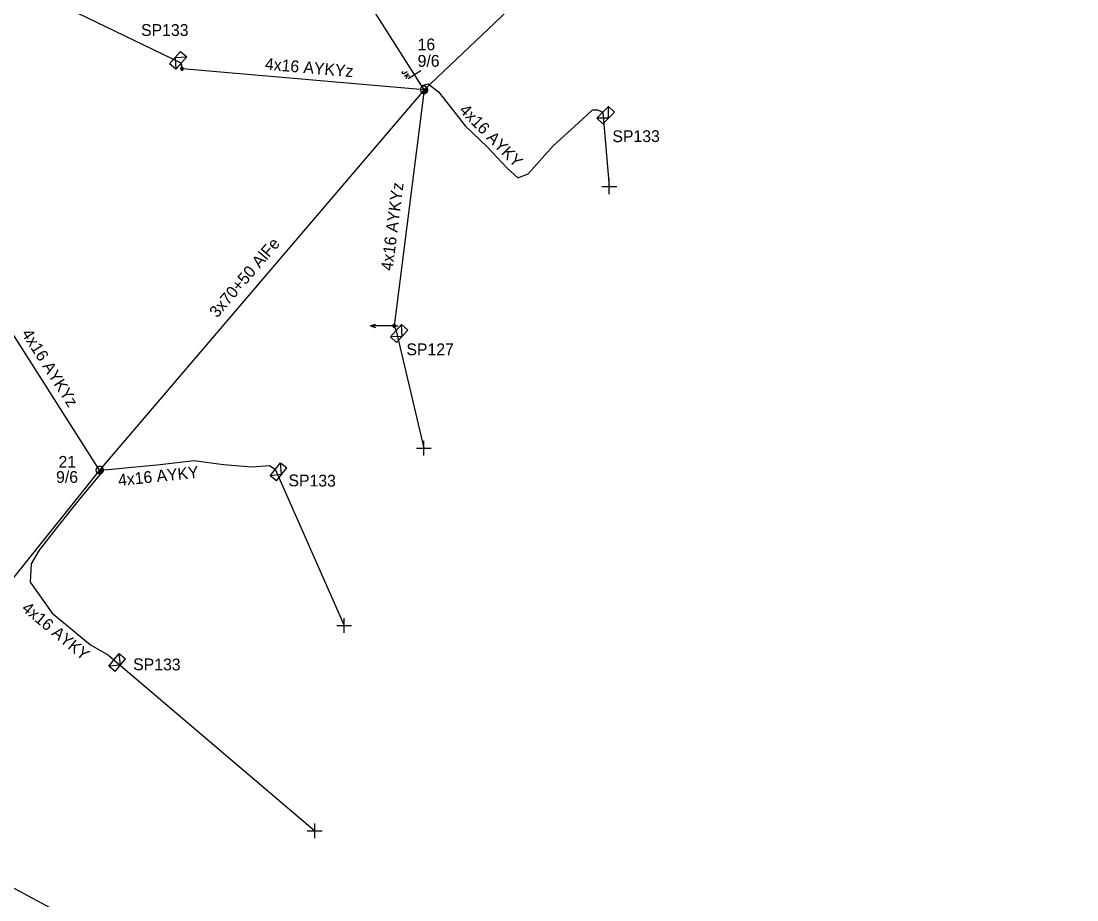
# Model space of a CAD drawing. Extents: x -748492 to -735633, y -1146251 to -1139940.
# Drawn here: x -742999.5 to -742910.1, y -1140234.1 to -1140159.7 of the extents above; entities that cross this region are included whole.
import ezdxf

# ---------------------------------------------------------------- set-up
doc = ezdxf.new("R2010")
doc.units = 0
for name, color, linetype in [('Vrstva 1', 7, 'Continuous'), ('Vrstva 12', 7, 'Continuous'), ('Vrstva 13', 7, 'Continuous'), ('Vrstva 14', 7, 'Continuous'), ('Vrstva 15', 7, 'Continuous'), ('Vrstva 18', 7, 'Continuous'), ('Vrstva 2', 7, 'Continuous'), ('Vrstva 31', 7, 'Continuous'), ('Vrstva 33', 7, 'Continuous'), ('Vrstva 34', 7, 'Continuous'), ('Vrstva 52', 7, 'Continuous'), ('Vrstva 54', 7, 'Continuous'), ('Vrstva 55', 7, 'Continuous'), ('Vrstva 59', 7, 'Continuous'), ('Vrstva 9', 7, 'Continuous')]:
    doc.layers.add(name, color=color, linetype=linetype)

# ---------------------------------------------------------------- blocks, each defined once
blk = doc.blocks.new('NN440')
at = {"layer": 'Vrstva 2'}
for points in [[(0.63, 0), (0.63, 0.06), (0.62, 0.13), (0.6, 0.19), (0.58, 0.25), (0.55, 0.31), (0.51, 0.37), (0.47, 0.42), (0.42, 0.46), (0.37, 0.51), (0.32, 0.54), (0.26, 0.57), (0.2, 0.59), (0.13, 0.61), (0.07, 0.62), (0, 0.63), (-0.06, 0.62), (-0.13, 0.61), (-0.19, 0.59), (-0.26, 0.57), (-0.31, 0.54), (-0.37, 0.51), (-0.42, 0.46), (-0.47, 0.42), (-0.51, 0.37), (-0.54, 0.31), (-0.57, 0.25), (-0.6, 0.19), (-0.62, 0.13), (-0.63, 0.06), (-0.63, 0), (-0.63, -0.07), (-0.62, -0.14), (-0.6, -0.2), (-0.57, -0.26), (-0.54, -0.32), (-0.51, -0.37), (-0.47, -0.43), (-0.42, -0.47), (-0.37, -0.51), (-0.31, -0.55), (-0.26, -0.58), (-0.19, -0.6), (-0.13, -0.62), (-0.06, -0.63), (0, -0.63), (0.07, -0.63), (0.13, -0.62), (0.2, -0.6), (0.26, -0.58), (0.32, -0.55), (0.37, -0.51), (0.42, -0.47), (0.47, -0.43), (0.51, -0.37), (0.55, -0.32), (0.58, -0.26), (0.6, -0.2), (0.62, -0.14), (0.63, -0.07), (0.63, 0)], [(-0.63, 0), (0.63, 0)], [(-0.6, -0.18), (0.57, -0.18)], [(-0.51, -0.32), (0.5, -0.32)], [(-0.37, -0.47), (0.35, -0.47)]]:
    blk.add_lwpolyline(points, dxfattribs=at)
blk = doc.blocks.new('NN560')
at = {"layer": 'Vrstva 2'}
for points in [[(1.999, -0.001), (1.59, 0.141)], [(0, -0.001), (1.999, -0.001)], [(1.999, -0.001), (1.59, -0.134)]]:
    blk.add_lwpolyline(points, dxfattribs=at)
blk = doc.blocks.new('NN840')
at = {"layer": 'Vrstva 15'}
for points in [[(0.003, 0.619), (0.003, -0.631)], [(-0.745, -0.71), (-0.745, -0.66)], [(-0.73, -0.764), (-0.745, -0.71)], [(-0.657, -0.798), (-0.73, -0.764)], [(-0.627, -0.798), (-0.657, -0.798)], [(-0.558, -0.764), (-0.627, -0.798)], [(-0.538, -0.71), (-0.558, -0.764)], [(-0.538, -0.385), (-0.538, -0.71)], [(-0.332, -0.385), (-0.332, -0.798)], [(-0.332, -0.641), (-0.125, -0.385)], [(-0.263, -0.557), (-0.091, -0.798)]]:
    blk.add_lwpolyline(points, dxfattribs=at)
blk = doc.blocks.new('NN800')
at = {"layer": 'Vrstva 1'}
for points in [[(-0.442, 0.442), (0.442, -0.442)], [(-0.442, -0.442), (0.442, 0.442)]]:
    blk.add_lwpolyline(points, dxfattribs=at)
blk = doc.blocks.new('NN630')
at = {"layer": 'Vrstva 9'}
for points in [[(-0.003, -0.7), (-0.703, 0)], [(-0.703, -0.7), (-0.703, 0), (0.697, 0), (0.697, -0.7)], [(-0.703, -0.7), (0.697, -0.7)], [(-0.003, -0.7), (0.697, 0)]]:
    blk.add_lwpolyline(points, dxfattribs=at)
blk = doc.blocks.new('NN500')
at = {"layer": 'Vrstva 2'}
for points in [[(0, -0.24), (0.02, -0.23), (0.05, -0.23), (0.07, -0.22), (0.09, -0.22), (0.12, -0.2), (0.14, -0.19), (0.16, -0.18), (0.17, -0.16), (0.19, -0.14), (0.2, -0.12), (0.21, -0.1), (0.22, -0.07), (0.23, -0.05), (0.23, -0.02), (0.23, 0), (0.23, 0.02), (0.23, 0.05), (0.22, 0.07), (0.21, 0.1), (0.2, 0.12), (0.19, 0.14), (0.17, 0.16), (0.16, 0.17), (0.14, 0.19), (0.12, 0.2), (0.09, 0.21), (0.07, 0.22), (0.05, 0.23), (0.02, 0.23), (0, 0.23), (-0.03, 0.23), (-0.05, 0.23), (-0.07, 0.22), (-0.1, 0.21), (-0.12, 0.2), (-0.14, 0.19), (-0.16, 0.17), (-0.18, 0.16), (-0.19, 0.14), (-0.2, 0.12), (-0.22, 0.1), (-0.22, 0.07), (-0.23, 0.05), (-0.23, 0.02), (-0.24, 0), (-0.23, -0.02), (-0.23, -0.05), (-0.22, -0.07), (-0.22, -0.1), (-0.2, -0.12), (-0.19, -0.14), (-0.18, -0.16), (-0.16, -0.18), (-0.14, -0.19), (-0.12, -0.2), (-0.1, -0.22), (-0.07, -0.22), (-0.05, -0.23), (-0.03, -0.23), (0, -0.24)], [(0, -0.24), (0.02, -0.23), (0.05, -0.23), (0.07, -0.22), (0.09, -0.22), (0.12, -0.2), (0.14, -0.19), (0.16, -0.18), (0.17, -0.16), (0.19, -0.14), (0.2, -0.12), (0.21, -0.1), (0.22, -0.07), (0.23, -0.05), (0.23, -0.02), (0.23, 0), (0.23, 0.02), (0.23, 0.05), (0.22, 0.07), (0.21, 0.1), (0.2, 0.12), (0.19, 0.14), (0.17, 0.16), (0.16, 0.17), (0.14, 0.19), (0.12, 0.2), (0.09, 0.21), (0.07, 0.22), (0.05, 0.23), (0.02, 0.23), (0, 0.23), (-0.03, 0.23), (-0.05, 0.23), (-0.07, 0.22), (-0.1, 0.21), (-0.12, 0.2), (-0.14, 0.19), (-0.16, 0.17), (-0.18, 0.16), (-0.19, 0.14), (-0.2, 0.12), (-0.22, 0.1), (-0.22, 0.07), (-0.23, 0.05), (-0.23, 0.02), (-0.24, 0), (-0.23, -0.02), (-0.23, -0.05), (-0.22, -0.07), (-0.22, -0.1), (-0.2, -0.12), (-0.19, -0.14), (-0.18, -0.16), (-0.16, -0.18), (-0.14, -0.19), (-0.12, -0.2), (-0.1, -0.22), (-0.07, -0.22), (-0.05, -0.23), (-0.03, -0.23), (0, -0.24)], [(0, -0.21), (0.02, -0.2), (0.04, -0.2), (0.06, -0.2), (0.08, -0.19), (0.1, -0.18), (0.12, -0.17), (0.14, -0.15), (0.15, -0.14), (0.16, -0.12), (0.18, -0.1), (0.19, -0.08), (0.19, -0.06), (0.2, -0.04), (0.2, -0.02), (0.2, 0), (0.2, 0.02), (0.2, 0.04), (0.19, 0.06), (0.19, 0.08), (0.18, 0.1), (0.16, 0.12), (0.15, 0.14), (0.14, 0.15), (0.12, 0.17), (0.1, 0.18), (0.08, 0.19), (0.06, 0.19), (0.04, 0.2), (0.02, 0.2), (0, 0.2), (-0.02, 0.2), (-0.04, 0.2), (-0.06, 0.19), (-0.08, 0.19), (-0.1, 0.18), (-0.12, 0.17), (-0.14, 0.15), (-0.15, 0.14), (-0.17, 0.12), (-0.18, 0.1), (-0.19, 0.08), (-0.2, 0.06), (-0.2, 0.04), (-0.21, 0.02), (-0.21, 0), (-0.21, -0.02), (-0.2, -0.04), (-0.2, -0.06), (-0.19, -0.08), (-0.18, -0.1), (-0.17, -0.12), (-0.15, -0.14), (-0.14, -0.15), (-0.12, -0.17), (-0.1, -0.18), (-0.08, -0.19), (-0.06, -0.2), (-0.04, -0.2), (-0.02, -0.2), (0, -0.21)], [(0, -0.18), (0.02, -0.18), (0.04, -0.17), (0.05, -0.17), (0.07, -0.16), (0.09, -0.15), (0.1, -0.14), (0.12, -0.13), (0.13, -0.12), (0.14, -0.1), (0.15, -0.09), (0.16, -0.07), (0.17, -0.05), (0.17, -0.04), (0.17, -0.02), (0.17, 0), (0.17, 0.02), (0.17, 0.04), (0.17, 0.05), (0.16, 0.07), (0.15, 0.09), (0.14, 0.1), (0.13, 0.12), (0.12, 0.13), (0.1, 0.14), (0.09, 0.15), (0.07, 0.16), (0.05, 0.17), (0.04, 0.17), (0.02, 0.17), (0, 0.18), (-0.02, 0.17), (-0.04, 0.17), (-0.06, 0.17), (-0.07, 0.16), (-0.09, 0.15), (-0.1, 0.14), (-0.12, 0.13), (-0.13, 0.12), (-0.14, 0.1), (-0.15, 0.09), (-0.16, 0.07), (-0.17, 0.05), (-0.17, 0.04), (-0.18, 0.02), (-0.18, 0), (-0.18, -0.02), (-0.17, -0.04), (-0.17, -0.05), (-0.16, -0.07), (-0.15, -0.09), (-0.14, -0.1), (-0.13, -0.12), (-0.12, -0.13), (-0.1, -0.14), (-0.09, -0.15), (-0.07, -0.16), (-0.06, -0.17), (-0.04, -0.17), (-0.02, -0.18), (0, -0.18)], [(0, -0.15), (0.01, -0.15), (0.03, -0.14), (0.04, -0.14), (0.06, -0.13), (0.07, -0.13), (0.08, -0.12), (0.1, -0.11), (0.11, -0.1), (0.12, -0.09), (0.13, -0.07), (0.13, -0.06), (0.14, -0.05), (0.14, -0.03), (0.14, -0.02), (0.14, 0), (0.14, 0.01), (0.14, 0.03), (0.14, 0.04), (0.13, 0.06), (0.13, 0.07), (0.12, 0.09), (0.11, 0.1), (0.1, 0.11), (0.08, 0.12), (0.07, 0.13), (0.06, 0.13), (0.04, 0.14), (0.03, 0.14), (0.01, 0.14), (0, 0.15), (-0.02, 0.14), (-0.03, 0.14), (-0.05, 0.14), (-0.06, 0.13), (-0.07, 0.13), (-0.09, 0.12), (-0.1, 0.11), (-0.11, 0.1), (-0.12, 0.09), (-0.13, 0.07), (-0.13, 0.06), (-0.14, 0.04), (-0.14, 0.03), (-0.15, 0.01), (-0.15, 0), (-0.15, -0.02), (-0.14, -0.03), (-0.14, -0.05), (-0.13, -0.06), (-0.13, -0.07), (-0.12, -0.09), (-0.11, -0.1), (-0.1, -0.11), (-0.09, -0.12), (-0.07, -0.13), (-0.06, -0.13), (-0.05, -0.14), (-0.03, -0.14), (-0.02, -0.15), (0, -0.15)], [(0, -0.12), (0.01, -0.12), (0.02, -0.11), (0.03, -0.11), (0.05, -0.11), (0.06, -0.1), (0.07, -0.09), (0.08, -0.09), (0.09, -0.08), (0.09, -0.07), (0.1, -0.06), (0.11, -0.05), (0.11, -0.04), (0.11, -0.02), (0.11, -0.01), (0.12, 0), (0.11, 0.01), (0.11, 0.02), (0.11, 0.04), (0.11, 0.05), (0.1, 0.06), (0.09, 0.07), (0.09, 0.08), (0.08, 0.09), (0.07, 0.09), (0.06, 0.1), (0.05, 0.11), (0.03, 0.11), (0.02, 0.11), (0.01, 0.12), (0, 0.12), (-0.01, 0.12), (-0.03, 0.11), (-0.04, 0.11), (-0.05, 0.11), (-0.06, 0.1), (-0.07, 0.09), (-0.08, 0.09), (-0.09, 0.08), (-0.1, 0.07), (-0.1, 0.06), (-0.11, 0.05), (-0.11, 0.04), (-0.12, 0.02), (-0.12, 0.01), (-0.12, 0), (-0.12, -0.01), (-0.12, -0.02), (-0.11, -0.04), (-0.11, -0.05), (-0.1, -0.06), (-0.1, -0.07), (-0.09, -0.08), (-0.08, -0.09), (-0.07, -0.09), (-0.06, -0.1), (-0.05, -0.11), (-0.04, -0.11), (-0.03, -0.11), (-0.01, -0.12), (0, -0.12)], [(0, -0.09), (0.01, -0.09), (0.02, -0.09), (0.03, -0.08), (0.03, -0.08), (0.04, -0.08), (0.05, -0.07), (0.06, -0.07), (0.06, -0.06), (0.07, -0.05), (0.07, -0.04), (0.08, -0.04), (0.08, -0.03), (0.08, -0.02), (0.09, -0.01), (0.09, 0), (0.09, 0.01), (0.08, 0.02), (0.08, 0.03), (0.08, 0.03), (0.07, 0.04), (0.07, 0.05), (0.06, 0.06), (0.06, 0.06), (0.05, 0.07), (0.04, 0.07), (0.03, 0.08), (0.03, 0.08), (0.02, 0.08), (0.01, 0.09), (0, 0.09), (-0.01, 0.09), (-0.02, 0.08), (-0.03, 0.08), (-0.04, 0.08), (-0.04, 0.07), (-0.05, 0.07), (-0.06, 0.06), (-0.07, 0.06), (-0.07, 0.05), (-0.08, 0.04), (-0.08, 0.03), (-0.08, 0.03), (-0.09, 0.02), (-0.09, 0.01), (-0.09, 0), (-0.09, -0.01), (-0.09, -0.02), (-0.08, -0.03), (-0.08, -0.04), (-0.08, -0.04), (-0.07, -0.05), (-0.07, -0.06), (-0.06, -0.07), (-0.05, -0.07), (-0.04, -0.08), (-0.04, -0.08), (-0.03, -0.08), (-0.02, -0.09), (-0.01, -0.09), (0, -0.09)], [(0, -0.06), (0, -0.06), (0.01, -0.06), (0.02, -0.05), (0.02, -0.05), (0.03, -0.05), (0.03, -0.05), (0.04, -0.04), (0.04, -0.04), (0.05, -0.03), (0.05, -0.03), (0.05, -0.02), (0.05, -0.02), (0.05, -0.01), (0.06, -0.01), (0.06, 0), (0.06, 0.01), (0.05, 0.01), (0.05, 0.02), (0.05, 0.02), (0.05, 0.03), (0.05, 0.03), (0.04, 0.04), (0.04, 0.04), (0.03, 0.05), (0.03, 0.05), (0.02, 0.05), (0.02, 0.05), (0.01, 0.06), (0, 0.06), (0, 0.06), (-0.01, 0.06), (-0.01, 0.06), (-0.02, 0.05), (-0.02, 0.05), (-0.03, 0.05), (-0.03, 0.05), (-0.04, 0.04), (-0.04, 0.04), (-0.05, 0.03), (-0.05, 0.03), (-0.05, 0.02), (-0.06, 0.02), (-0.06, 0.01), (-0.06, 0.01), (-0.06, 0), (-0.06, -0.01), (-0.06, -0.01), (-0.06, -0.02), (-0.05, -0.02), (-0.05, -0.03), (-0.05, -0.03), (-0.04, -0.04), (-0.04, -0.04), (-0.03, -0.05), (-0.03, -0.05), (-0.02, -0.05), (-0.02, -0.05), (-0.01, -0.06), (-0.01, -0.06), (0, -0.06)], [(0, -0.03), (0, -0.03), (0, -0.03), (0.01, -0.03), (0.01, -0.03), (0.01, -0.02), (0.02, -0.02), (0.02, -0.02), (0.02, -0.02), (0.02, -0.02), (0.02, -0.01), (0.02, -0.01), (0.03, -0.01), (0.03, -0.01), (0.03, 0), (0.03, 0), (0.03, 0), (0.03, 0.01), (0.03, 0.01), (0.02, 0.01), (0.02, 0.01), (0.02, 0.02), (0.02, 0.02), (0.02, 0.02), (0.02, 0.02), (0.01, 0.02), (0.01, 0.02), (0.01, 0.03), (0, 0.03), (0, 0.03), (0, 0.03), (0, 0.03), (-0.01, 0.03), (-0.01, 0.03), (-0.01, 0.02), (-0.02, 0.02), (-0.02, 0.02), (-0.02, 0.02), (-0.02, 0.02), (-0.02, 0.02), (-0.03, 0.01), (-0.03, 0.01), (-0.03, 0.01), (-0.03, 0.01), (-0.03, 0), (-0.03, 0), (-0.03, 0), (-0.03, -0.01), (-0.03, -0.01), (-0.03, -0.01), (-0.03, -0.01), (-0.02, -0.02), (-0.02, -0.02), (-0.02, -0.02), (-0.02, -0.02), (-0.02, -0.02), (-0.01, -0.03), (-0.01, -0.03), (-0.01, -0.03), (0, -0.03), (0, -0.03)], [(0.23, 0), (0.7, 0)]]:
    blk.add_lwpolyline(points, dxfattribs=at)

msp = doc.modelspace()

# ---------------------------------------------------------------- linework, layer by layer
at = {"layer": 'Vrstva 1'}
for points in [[(-742910.111, -1140120.298), (-742943.6, -1140144.92), (-742965.37, -1140165.561)], [(-742965.37, -1140165.561), (-742992.83, -1140197.73), (-743013.94, -1140224.06), (-743032.181, -1140246.944), (-743049.85, -1140269.329), (-743074.31, -1140304.729)]]:
    msp.add_lwpolyline(points, dxfattribs=at)
at = {"layer": 'Vrstva 52'}
for points in [[(-742965.37, -1140165.561), (-742975.32, -1140149.849)], [(-742965.37, -1140165.561), (-742965.58, -1140165.19), (-742965.02, -1140165.05), (-742964.16, -1140165.72), (-742963.425, -1140166.649), (-742961.88, -1140168.6), (-742960.03, -1140170.39), (-742958.33, -1140172.2), (-742957.44, -1140173.01), (-742956.56, -1140172.67), (-742954.44, -1140170.29), (-742952.34, -1140168.38), (-742951.11, -1140167.25), (-742950.68, -1140167.25), (-742950.24, -1140167.45)], [(-742992.83, -1140197.73), (-742991.807, -1140197.647), (-742990.915, -1140197.57), (-742990.68, -1140197.55), (-742987.72, -1140197.26), (-742984.86, -1140196.93), (-742982.35, -1140197.25), (-742979.96, -1140197.45), (-742978.44, -1140197.33), (-742977.97, -1140197.66)], [(-742992.83, -1140197.73), (-742992.79, -1140198.09), (-742993.448, -1140198.878), (-742994.46, -1140200.09), (-742996.46, -1140202.58), (-742997.96, -1140204.52), (-742998.64, -1140205.66), (-742998.7, -1140207.2), (-742996.84, -1140209.85), (-742993.6, -1140212.51), (-742992.09, -1140213.4), (-742991.62, -1140213.79)]]:
    msp.add_lwpolyline(points, dxfattribs=at)
at = {"layer": 'Vrstva 54'}
for points in [[(-742965.37, -1140165.561), (-742985.86, -1140163.781), (-742985.931, -1140163.3)], [(-742965.37, -1140165.561), (-742967.9, -1140185.52), (-742967.74, -1140185.939)], [(-742992.83, -1140197.73), (-743001.929, -1140183.491), (-743002.14, -1140183.149)]]:
    msp.add_lwpolyline(points, dxfattribs=at)
at = {"layer": 'Vrstva 59'}
for points in [[(-742985.931, -1140163.3), (-743000.25, -1140156.38)], [(-742950.24, -1140167.45), (-742949.69, -1140173.75)], [(-742967.74, -1140185.94), (-742965.38, -1140195.88)], [(-742977.97, -1140197.66), (-742972.13, -1140210.88)], [(-742991.62, -1140213.79), (-742974.63, -1140228.25)], [(-743005.62, -1140230.13), (-742985.503, -1140240.95)]]:
    msp.add_lwpolyline(points, dxfattribs=at)

# ---------------------------------------------------------------- block references
at = {"layer": 'Vrstva 13'}
for name, p, xscale, yscale, rotation in [('NN500', (-742985.86, -1140163.78), 0.5, 0.5, 91.12400000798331), ('NN440', (-742965.37, -1140165.56), 0.5, 0.5, 47.39576946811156), ('NN500', (-742967.9, -1140185.52), 0.49999999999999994, 0.5000000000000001, 0.4640000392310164), ('NN440', (-742992.83, -1140197.73), 0.49999999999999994, 0.49999999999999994, 50.331997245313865)]:
    msp.add_blockref(name, p, dxfattribs=dict(at, xscale=xscale, yscale=yscale, rotation=rotation))
at = {"layer": 'Vrstva 13', "rotation": -179.53626935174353}
msp.add_blockref('NN560', (-742967.9, -1140185.52), dxfattribs=at)
at = {"layer": 'Vrstva 18', "rotation": -57.65423730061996}
msp.add_blockref('NN840', (-742966.181, -1140164.28), dxfattribs=at)
at = {"layer": 'Vrstva 31'}
for p, rotation in [((-742985.93, -1140163.3), -131.62577775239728), ((-742950.24, -1140167.45), 44.74074719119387), ((-742967.74, -1140185.94), 47.39576941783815), ((-742977.97, -1140197.66), 51.25905871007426), ((-742991.62, -1140213.79), 50.7626480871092)]:
    msp.add_blockref('NN630', p, dxfattribs=dict(at, rotation=rotation))
at = {"layer": 'Vrstva 34'}
for p, rotation in [((-742949.69, -1140173.75), 44.99999995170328), ((-742965.38, -1140195.88), 45), ((-742972.13, -1140210.88), 45), ((-742974.63, -1140228.25), 45)]:
    msp.add_blockref('NN800', p, dxfattribs=dict(at, rotation=rotation))

# ---------------------------------------------------------------- texts
at = {"layer": 'Vrstva 12'}
for rotation, p in [(0.149, (-742965.915, -1140163.615)), (359.964, (-742996.519, -1140198.815))]:
    msp.add_text('9/6', height=1, rotation=rotation, dxfattribs=at).set_placement(p)
at = {"layer": 'Vrstva 14'}
for s, rotation, p in [('16', 0.178, (-742965.917, -1140162.219)), ('21', 359.986, (-742996.315, -1140197.536))]:
    msp.add_text(s, height=1, rotation=rotation, dxfattribs=at).set_placement(p)
at = {"layer": 'Vrstva 2'}
msp.add_text('3x70+50 AlFe', height=1, rotation=49.516, dxfattribs=at).set_placement((-742982.884, -1140184.913))
at = {"layer": 'Vrstva 33'}
for s, rotation, p in [('SP133', 359.961, (-742989.328, -1140160.999)), ('SP133', 0.232, (-742949.426, -1140169.99)), ('SP127', 0.049, (-742966.865, -1140188.018)), ('SP133', 359.587, (-742976.853, -1140199.102)), ('SP133', 359.714, (-742989.998, -1140214.662))]:
    msp.add_text(s, height=1, rotation=rotation, dxfattribs=at).set_placement(p)
at = {"layer": 'Vrstva 54'}
for rotation, p in [(314.81, (-742962.462, -1140167.351)), (6.013, (-742991.218, -1140199.086)), (320.614, (-742999.499, -1140209.559))]:
    msp.add_text('4x16 AYKY', height=1, rotation=rotation, dxfattribs=at).set_placement(p)
at = {"layer": 'Vrstva 55'}
for rotation, p in [(355.035, (-742978.872, -1140163.846)), (82.776, (-742968.038, -1140180.908)), (302.58, (-742999.481, -1140186.179))]:
    msp.add_text('4x16 AYKYz', height=1, rotation=rotation, dxfattribs=at).set_placement(p)

doc.saveas('drawing.dxf')
